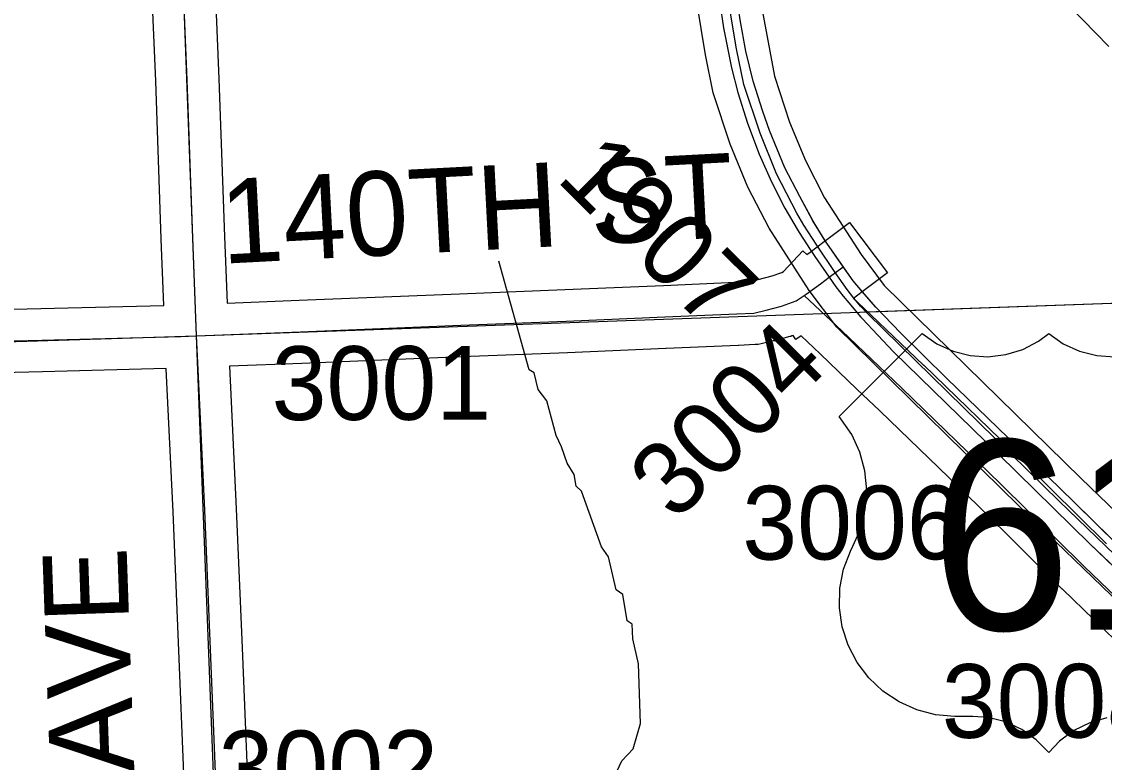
# Model space of a CAD drawing. Extents: x 128.7 to 185.5, y -21.4 to 12.6.
# Drawn here: x 145.758 to 146.785, y 0.252 to 0.955 of the extents above; entities that cross this region are included whole.
import ezdxf

# ---------------------------------------------------------------- set-up
doc = ezdxf.new("R2010")
doc.units = 0
for name, color, linetype in [('tdCoDivCarto', 7, 'Continuous'), ('tdCoHydroRiver', 7, 'Continuous'), ('tdCoPriCL', 7, 'Continuous'), ('tdCoPriDiv', 7, 'Continuous'), ('tdCoPrimary', 7, 'Continuous'), ('tdCoSecRdNmbr', 7, 'Continuous'), ('tdCoSecRdTxt', 7, 'Continuous'), ('tdCoSecRteBand', 7, 'Continuous'), ('tdCoSecRteCL', 7, 'Continuous'), ('tdCoSectLine', 7, 'Continuous'), ('tdCoSectLinePart', 7, 'Continuous'), ('tdCoShieldUsRte', 7, 'Continuous'), ('tdCoSurfConc', 7, 'Continuous'), ('tdCoSurfGravel', 7, 'Continuous'), ('tdCoTwpBndryShd', 7, 'Continuous')]:
    doc.layers.add(name, color=color, linetype=linetype)

msp = doc.modelspace()

# ---------------------------------------------------------------- linework, layer by layer
at = {"layer": 'tdCoDivCarto'}
for p, q in [((146.4204, 0.9729), (146.4238, 0.9497)), ((146.445, 0.9274), (146.4399, 0.957)), ((146.4238, 0.9497), (146.4317, 0.9115)), ((146.4522, 0.8988), (146.445, 0.9274)), ((146.4317, 0.9115), (146.4376, 0.8881)), ((146.4613, 0.87), (146.4522, 0.8988)), ((146.4376, 0.8881), (146.4468, 0.8592)), ((146.4675, 0.852), (146.4613, 0.87)), ((146.4468, 0.8592), (146.4579, 0.8296)), ((146.482, 0.8167), (146.4675, 0.852)), ((146.4579, 0.8296), (146.4695, 0.8035)), ((146.4963, 0.7893), (146.482, 0.8167)), ((146.4695, 0.8035), (146.482, 0.7783)), ((146.5087, 0.7664), (146.4963, 0.7893)), ((146.482, 0.7783), (146.4939, 0.7583)), ((146.5089, 0.7661), (146.5087, 0.7664)), ((146.5205, 0.7474), (146.5089, 0.7661)), ((146.5205, 0.7474), (146.5089, 0.7661)), ((146.4939, 0.7583), (146.4956, 0.7554)), ((146.4956, 0.7554), (146.5063, 0.7391)), ((146.522, 0.745), (146.5205, 0.7474)), ((146.5381, 0.722), (146.522, 0.745)), ((146.5063, 0.7391), (146.5106, 0.7325)), ((146.5106, 0.7325), (146.5241, 0.713)), ((146.5469, 0.7094), (146.5381, 0.722)), ((146.5241, 0.713), (146.5306, 0.7036)), ((146.5559, 0.699), (146.5469, 0.7094)), ((146.5306, 0.7036), (146.5375, 0.6947)), ((146.5686, 0.6843), (146.5559, 0.699)), ((146.5686, 0.6843), (146.5559, 0.699)), ((146.5375, 0.6947), (146.5428, 0.6885)), ((146.5428, 0.6885), (146.5543, 0.675)), ((146.5918, 0.6599), (146.5686, 0.6843)), ((146.5686, 0.6843), (146.5686, 0.6843)), ((146.5543, 0.675), (146.5556, 0.6736)), ((146.5556, 0.6736), (146.5851, 0.642)), ((146.6359, 0.6167), (146.5918, 0.6599)), ((146.5851, 0.642), (146.6852, 0.5445)), ((146.6941, 0.5602), (146.6359, 0.6167)), ((146.7568, 0.4993), (146.6941, 0.5602)), ((146.6852, 0.5445), (146.7716, 0.4597)), ((146.8187, 0.4382), (146.7568, 0.4993)), ((146.7716, 0.4597), (146.8253, 0.4082))]:
    msp.add_line(p, q, dxfattribs=at)
for points in [[(146.4075, 1.6164), (146.4085, 1.5347), (146.4105, 1.4153), (146.4127, 1.2861), (146.4145, 1.1657), (146.4157, 1.0553), (146.4187, 0.9919), (146.4204, 0.9729), (146.4238, 0.9497), (146.4317, 0.9115), (146.4376, 0.8881), (146.4468, 0.8592), (146.4579, 0.8296), (146.4695, 0.8035), (146.482, 0.7783), (146.4939, 0.7583)], [(146.4075, 1.6164), (146.4085, 1.5347), (146.4105, 1.4153), (146.4127, 1.2861), (146.4145, 1.1657), (146.4157, 1.0553), (146.4187, 0.9919), (146.4204, 0.9729), (146.4238, 0.9497), (146.4317, 0.9115), (146.4376, 0.8881), (146.4468, 0.8592), (146.4579, 0.8296), (146.4695, 0.8035), (146.482, 0.7783), (146.4939, 0.7583)], [(146.4075, 1.6164), (146.4085, 1.5347), (146.4105, 1.4153), (146.4127, 1.2861), (146.4145, 1.1657), (146.4157, 1.0553), (146.4187, 0.9919), (146.4204, 0.9729), (146.4238, 0.9497), (146.4317, 0.9115), (146.4376, 0.8881), (146.4468, 0.8592), (146.4579, 0.8296), (146.4695, 0.8035), (146.482, 0.7783), (146.4939, 0.7583)], [(146.5086, 0.7666), (146.4963, 0.7893), (146.482, 0.8167), (146.4675, 0.852), (146.4613, 0.87), (146.4522, 0.8988), (146.445, 0.9274), (146.4399, 0.957), (146.4367, 0.979), (146.4347, 1.0041), (146.4325, 1.0823), (146.4305, 1.194), (146.429, 1.3154), (146.4273, 1.4438), (146.4253, 1.5652), (146.4245, 1.6166)], [(146.5089, 0.7661), (146.5087, 0.7664), (146.4963, 0.7893), (146.482, 0.8167), (146.4675, 0.852), (146.4613, 0.87), (146.4522, 0.8988), (146.445, 0.9274), (146.4399, 0.957), (146.4367, 0.979), (146.4347, 1.0041), (146.4325, 1.0823), (146.4305, 1.194), (146.429, 1.3154), (146.4273, 1.4438), (146.4253, 1.5652), (146.4245, 1.6161)], [(146.5089, 0.7661), (146.5087, 0.7664), (146.4963, 0.7893), (146.482, 0.8167), (146.4675, 0.852), (146.4613, 0.87), (146.4522, 0.8988), (146.445, 0.9274), (146.4399, 0.957), (146.4367, 0.979), (146.4347, 1.0041), (146.4325, 1.0823), (146.4305, 1.194), (146.429, 1.3154), (146.4273, 1.4438), (146.4253, 1.5652), (146.4245, 1.6161)], [(146.5201, 0.7479), (146.5087, 0.7664), (146.5086, 0.7666)], [(146.5205, 0.7474), (146.5089, 0.7661)], [(146.4939, 0.7583), (146.4956, 0.7554), (146.5063, 0.7391)], [(146.4939, 0.7583), (146.4956, 0.7554), (146.5063, 0.7391)], [(146.4939, 0.7583), (146.4956, 0.7554), (146.5063, 0.7391)], [(146.5377, 0.7225), (146.522, 0.745), (146.5201, 0.7479)], [(146.5381, 0.722), (146.522, 0.745), (146.5205, 0.7474)], [(146.5381, 0.722), (146.522, 0.745), (146.5205, 0.7474)], [(146.5063, 0.7391), (146.5106, 0.7325), (146.5241, 0.713)], [(146.5063, 0.7391), (146.5106, 0.7325), (146.5241, 0.713)], [(146.5063, 0.7391), (146.5106, 0.7325), (146.5241, 0.713)], [(146.5555, 0.6994), (146.5469, 0.7094), (146.5377, 0.7225)], [(146.5559, 0.699), (146.5469, 0.7094), (146.5381, 0.722)], [(146.5559, 0.699), (146.5469, 0.7094), (146.5381, 0.722)], [(146.5241, 0.713), (146.5306, 0.7036), (146.5375, 0.6947), (146.5428, 0.6885)], [(146.5241, 0.713), (146.5306, 0.7036), (146.5375, 0.6947), (146.5428, 0.6885)], [(146.5241, 0.713), (146.5306, 0.7036), (146.5375, 0.6947), (146.5428, 0.6885)], [(146.5681, 0.6848), (146.5555, 0.6994)], [(146.5686, 0.6843), (146.5559, 0.699)], [(146.5428, 0.6885), (146.5543, 0.675), (146.5556, 0.6736)], [(146.5428, 0.6885), (146.5543, 0.675), (146.5556, 0.6736)], [(146.5428, 0.6885), (146.5543, 0.675), (146.5556, 0.6736)], [(147.272, -0.1789), (147.2579, -0.1522), (147.1908, -0.0252), (147.1661, 0.0212), (147.1348, 0.0779), (147.1131, 0.1124), (147.0872, 0.1514), (147.0751, 0.1681), (147.0554, 0.1948), (147.0253, 0.2315), (146.997, 0.2643), (146.9728, 0.2895), (146.9452, 0.3166), (146.9188, 0.3422), (146.8724, 0.3874), (146.8187, 0.4382), (146.7568, 0.4993), (146.6941, 0.5602), (146.6359, 0.6167), (146.5918, 0.6599), (146.5686, 0.6843), (146.5681, 0.6848)], [(147.2723, -0.1794), (147.2579, -0.1522), (147.1908, -0.0252), (147.1661, 0.0212), (147.1348, 0.0779), (147.1131, 0.1124), (147.0872, 0.1514), (147.0751, 0.1681), (147.0554, 0.1948), (147.0253, 0.2315), (146.997, 0.2643), (146.9728, 0.2895), (146.9452, 0.3166), (146.9188, 0.3422), (146.8724, 0.3874), (146.8187, 0.4382), (146.7568, 0.4993), (146.6941, 0.5602), (146.6359, 0.6167), (146.5918, 0.6599), (146.5686, 0.6843), (146.5686, 0.6843)], [(147.2723, -0.1794), (147.2579, -0.1522), (147.1908, -0.0252), (147.1661, 0.0212), (147.1348, 0.0779), (147.1131, 0.1124), (147.0872, 0.1514), (147.0751, 0.1681), (147.0554, 0.1948), (147.0253, 0.2315), (146.997, 0.2643), (146.9728, 0.2895), (146.9452, 0.3166), (146.9188, 0.3422), (146.8724, 0.3874), (146.8187, 0.4382), (146.7568, 0.4993), (146.6941, 0.5602), (146.6359, 0.6167), (146.5918, 0.6599), (146.5686, 0.6843), (146.5686, 0.6843)], [(146.5556, 0.6736), (146.5851, 0.642), (146.6852, 0.5445), (146.7716, 0.4597), (146.8253, 0.4082), (146.8719, 0.3638), (146.9775, 0.2585), (147.0302, 0.1986), (147.0421, 0.1835), (147.0724, 0.1423), (147.0951, 0.1081), (147.1124, 0.0812), (147.1294, 0.0513), (147.1607, -0.0051), (147.1824, -0.0463), (147.245, -0.1662), (147.2564, -0.1872)], [(146.5556, 0.6736), (146.5851, 0.642), (146.6852, 0.5445), (146.7716, 0.4597), (146.8253, 0.4082), (146.8719, 0.3638), (146.9775, 0.2585), (147.0302, 0.1986), (147.0421, 0.1835), (147.0724, 0.1423), (147.0951, 0.1081), (147.1124, 0.0812), (147.1294, 0.0513), (147.1607, -0.0051), (147.1824, -0.0463), (147.245, -0.1662), (147.2564, -0.1872)], [(146.5556, 0.6736), (146.5851, 0.642), (146.6852, 0.5445), (146.7716, 0.4597), (146.8253, 0.4082), (146.8719, 0.3638), (146.9775, 0.2585), (147.0302, 0.1986), (147.0421, 0.1835), (147.0724, 0.1423), (147.0951, 0.1081), (147.1124, 0.0812), (147.1294, 0.0513), (147.1607, -0.0051), (147.1824, -0.0463), (147.245, -0.1662), (147.2564, -0.1872)]]:
    msp.add_lwpolyline(points, dxfattribs=at)
at = {"layer": 'tdCoHydroRiver'}
for points in [[(146.7897, 0.9318), (146.7521, 0.97)], [(146.3186, 0.2346), (146.3275, 0.2538), (146.3381, 0.2652), (146.3452, 0.2891), (146.3434, 0.3459), (146.3379, 0.3694), (146.3374, 0.3836), (146.3326, 0.3866), (146.3286, 0.4117), (146.3221, 0.4162), (146.3148, 0.4475), (146.3082, 0.4568), (146.2891, 0.5098), (146.2842, 0.5144), (146.2823, 0.5254), (146.2756, 0.5362), (146.2703, 0.5518), (146.2653, 0.5627), (146.2563, 0.5955), (146.248, 0.6063), (146.2444, 0.622), (146.2395, 0.625), (146.2109, 0.7282)]]:
    msp.add_lwpolyline(points, dxfattribs=at)
at = {"layer": 'tdCoPriCL'}
msp.add_lwpolyline([(146.9277, 0.3216), (146.7425, 0.5002), (146.5605, 0.6785), (146.5539, 0.6852), (146.5477, 0.693), (146.5413, 0.7012), (146.53, 0.7173), (146.5125, 0.7434), (146.5001, 0.7623), (146.4935, 0.7737), (146.4743, 0.811), (146.4586, 0.8496), (146.4432, 0.8958), (146.4363, 0.9295), (146.4283, 0.9771)], dxfattribs=at)
at = {"layer": 'tdCoPriDiv'}
for points in [[(146.4582, 0.9803), (146.4722, 0.9036), (146.4867, 0.86), (146.5016, 0.8235), (146.5199, 0.7881), (146.5547, 0.7343), (146.5765, 0.7051), (146.7634, 0.5217), (146.9488, 0.3429)], [(146.9067, 0.3002), (146.7216, 0.4787), (146.5314, 0.6653), (146.5052, 0.7003), (146.4672, 0.7594), (146.447, 0.7984), (146.4304, 0.8392), (146.4142, 0.888), (146.4068, 0.924), (146.3985, 0.974)]]:
    msp.add_lwpolyline(points, dxfattribs=at)
at = {"layer": 'tdCoPrimary'}
for p, q in [((146.5205, 0.7474), (146.5089, 0.7661)), ((146.5205, 0.7474), (146.5089, 0.7661)), ((146.5686, 0.6843), (146.5559, 0.699)), ((146.5686, 0.6843), (146.5559, 0.699))]:
    msp.add_line(p, q, dxfattribs=at)
for points in [[(146.4075, 1.6164), (146.4085, 1.5347), (146.4105, 1.4153), (146.4127, 1.2861), (146.4145, 1.1657), (146.4157, 1.0553), (146.4187, 0.9919), (146.4204, 0.9729), (146.4238, 0.9497), (146.4317, 0.9115), (146.4376, 0.8881), (146.4468, 0.8592), (146.4579, 0.8296), (146.4695, 0.8035), (146.482, 0.7783), (146.4939, 0.7583)], [(146.4075, 1.6164), (146.4085, 1.5347), (146.4105, 1.4153), (146.4127, 1.2861), (146.4145, 1.1657), (146.4157, 1.0553), (146.4187, 0.9919), (146.4204, 0.9729), (146.4238, 0.9497), (146.4317, 0.9115), (146.4376, 0.8881), (146.4468, 0.8592), (146.4579, 0.8296), (146.4695, 0.8035), (146.482, 0.7783), (146.4939, 0.7583)], [(146.5089, 0.7661), (146.5087, 0.7664), (146.4963, 0.7893), (146.482, 0.8167), (146.4675, 0.852), (146.4613, 0.87), (146.4522, 0.8988), (146.445, 0.9274), (146.4399, 0.957), (146.4367, 0.979), (146.4347, 1.0041), (146.4325, 1.0823), (146.4305, 1.194), (146.429, 1.3154), (146.4273, 1.4438), (146.4253, 1.5652), (146.4245, 1.6161)], [(146.5089, 0.7661), (146.5087, 0.7664), (146.4963, 0.7893), (146.482, 0.8167), (146.4675, 0.852), (146.4613, 0.87), (146.4522, 0.8988), (146.445, 0.9274), (146.4399, 0.957), (146.4367, 0.979), (146.4347, 1.0041), (146.4325, 1.0823), (146.4305, 1.194), (146.429, 1.3154), (146.4273, 1.4438), (146.4253, 1.5652), (146.4245, 1.6161)], [(146.4204, 0.9729), (146.4238, 0.9497), (146.4317, 0.9115), (146.4376, 0.8881), (146.4468, 0.8592), (146.4579, 0.8296), (146.4695, 0.8035), (146.482, 0.7783), (146.4939, 0.7583), (146.4956, 0.7554), (146.5063, 0.7391), (146.5106, 0.7325), (146.5241, 0.713), (146.5306, 0.7036), (146.5375, 0.6947), (146.5428, 0.6885), (146.5543, 0.675), (146.5556, 0.6736), (146.5851, 0.642), (146.6852, 0.5445), (146.7716, 0.4597), (146.8253, 0.4082)], [(146.8187, 0.4382), (146.7568, 0.4993), (146.6941, 0.5602), (146.6359, 0.6167), (146.5918, 0.6599), (146.5686, 0.6843), (146.5686, 0.6843), (146.5559, 0.699), (146.5469, 0.7094), (146.5381, 0.722), (146.522, 0.745), (146.5205, 0.7474), (146.5089, 0.7661), (146.5087, 0.7664), (146.4963, 0.7893), (146.482, 0.8167), (146.4675, 0.852), (146.4613, 0.87), (146.4522, 0.8988), (146.445, 0.9274), (146.4399, 0.957)], [(146.4939, 0.7583), (146.4956, 0.7554), (146.5063, 0.7391)], [(146.4939, 0.7583), (146.4956, 0.7554), (146.5063, 0.7391)], [(146.5381, 0.722), (146.522, 0.745), (146.5205, 0.7474)], [(146.5381, 0.722), (146.522, 0.745), (146.5205, 0.7474)], [(146.5063, 0.7391), (146.5106, 0.7325), (146.5241, 0.713)], [(146.5063, 0.7391), (146.5106, 0.7325), (146.5241, 0.713)], [(146.5559, 0.699), (146.5469, 0.7094), (146.5381, 0.722)], [(146.5559, 0.699), (146.5469, 0.7094), (146.5381, 0.722)], [(146.5241, 0.713), (146.5306, 0.7036), (146.5375, 0.6947), (146.5428, 0.6885)], [(146.5241, 0.713), (146.5306, 0.7036), (146.5375, 0.6947), (146.5428, 0.6885)], [(146.5428, 0.6885), (146.5543, 0.675), (146.5556, 0.6736)], [(146.5428, 0.6885), (146.5543, 0.675), (146.5556, 0.6736)], [(147.2723, -0.1794), (147.2579, -0.1522), (147.1908, -0.0252), (147.1661, 0.0212), (147.1348, 0.0779), (147.1131, 0.1124), (147.0872, 0.1514), (147.0751, 0.1681), (147.0554, 0.1948), (147.0253, 0.2315), (146.997, 0.2643), (146.9728, 0.2895), (146.9452, 0.3166), (146.9188, 0.3422), (146.8724, 0.3874), (146.8187, 0.4382), (146.7568, 0.4993), (146.6941, 0.5602), (146.6359, 0.6167), (146.5918, 0.6599), (146.5686, 0.6843), (146.5686, 0.6843)], [(147.2723, -0.1794), (147.2579, -0.1522), (147.1908, -0.0252), (147.1661, 0.0212), (147.1348, 0.0779), (147.1131, 0.1124), (147.0872, 0.1514), (147.0751, 0.1681), (147.0554, 0.1948), (147.0253, 0.2315), (146.997, 0.2643), (146.9728, 0.2895), (146.9452, 0.3166), (146.9188, 0.3422), (146.8724, 0.3874), (146.8187, 0.4382), (146.7568, 0.4993), (146.6941, 0.5602), (146.6359, 0.6167), (146.5918, 0.6599), (146.5686, 0.6843), (146.5686, 0.6843)], [(146.5556, 0.6736), (146.5851, 0.642), (146.6852, 0.5445), (146.7716, 0.4597), (146.8253, 0.4082), (146.8719, 0.3638), (146.9775, 0.2585), (147.0302, 0.1986), (147.0421, 0.1835), (147.0724, 0.1423), (147.0951, 0.1081), (147.1124, 0.0812), (147.1294, 0.0513), (147.1607, -0.0051), (147.1824, -0.0463), (147.245, -0.1662), (147.2564, -0.1872)], [(146.5556, 0.6736), (146.5851, 0.642), (146.6852, 0.5445), (146.7716, 0.4597), (146.8253, 0.4082), (146.8719, 0.3638), (146.9775, 0.2585), (147.0302, 0.1986), (147.0421, 0.1835), (147.0724, 0.1423), (147.0951, 0.1081), (147.1124, 0.0812), (147.1294, 0.0513), (147.1607, -0.0051), (147.1824, -0.0463), (147.245, -0.1662), (147.2564, -0.1872)]]:
    msp.add_lwpolyline(points, dxfattribs=at)
at = {"layer": 'tdCoSecRteBand'}
for points in [[(144.9584, 0.6568), (145.0982, 0.6611), (145.2017, 0.6646), (145.2017, 0.6646), (145.2017, 0.6646), (145.3143, 0.6683), (145.4378, 0.6732), (145.4378, 0.6732), (145.4378, 0.6732), (145.5357, 0.6769), (145.5359, 0.6769), (145.5361, 0.6769), (145.6455, 0.6799), (145.6456, 0.6799), (145.6456, 0.6799), (145.7763, 0.6831), (145.8929, 0.6861), (145.8904, 0.7491), (145.8904, 0.7492), (145.8904, 0.7492), (145.8853, 0.8988), (145.8798, 1.0299)], [(145.9398, 1.0324), (145.9452, 0.9012), (145.9452, 0.9011), (145.9452, 0.901), (145.9504, 0.7514), (145.9529, 0.6883), (145.9529, 0.6883), (145.9529, 0.6883), (146.0215, 0.691), (146.1734, 0.6971), (146.1734, 0.6971), (146.1734, 0.6971), (146.2735, 0.7011), (146.3669, 0.705), (146.4354, 0.708), (146.4486, 0.7086), (146.457, 0.7106), (146.47, 0.7141), (146.4793, 0.7173), (146.4808, 0.7184), (146.4991, 0.7379), (146.503, 0.7343), (146.5062, 0.7367), (146.5195, 0.7467), (146.5434, 0.7648), (146.5796, 0.7169), (146.5556, 0.6988), (146.5474, 0.6926), (146.5568, 0.6837), (146.5569, 0.6836), (146.557, 0.6835), (146.5921, 0.65), (146.6137, 0.6293), (146.6138, 0.6292), (146.6139, 0.6292), (146.7073, 0.5387), (146.7074, 0.5385), (146.7075, 0.5384), (146.7873, 0.4597)], [(146.4926, 0.6538), (146.4901, 0.6575), (146.4888, 0.6571), (146.4878, 0.6567), (146.4868, 0.6565), (146.4722, 0.6525), (146.4717, 0.6524), (146.4712, 0.6523), (146.4596, 0.6495), (146.4569, 0.6489), (146.4541, 0.6488), (146.4381, 0.648), (146.4381, 0.648), (146.438, 0.648), (146.3695, 0.6451), (146.3695, 0.6451), (146.3694, 0.6451), (146.276, 0.6411), (146.2759, 0.6411), (146.2759, 0.6411), (146.1758, 0.6372), (146.0239, 0.631), (146.0239, 0.631), (146.0239, 0.631), (145.9553, 0.6283), (145.9617, 0.493), (145.9617, 0.4929), (145.9617, 0.4928), (145.9669, 0.3685), (145.9669, 0.3685), (145.9669, 0.3685), (145.9723, 0.2361)], [(146.8057, 0.3586), (146.7455, 0.4166), (146.7454, 0.4167), (146.7453, 0.4168), (146.6655, 0.4957), (146.5722, 0.586), (146.5506, 0.6066), (146.5156, 0.6401), (146.4975, 0.6571), (146.4926, 0.6538)], [(145.7456, -0.323), (145.8648, -0.319), (145.9316, -0.3163), (145.9299, -0.2754), (145.9245, -0.1447), (145.9245, -0.1447), (145.9245, -0.1446), (145.9191, -0.0098), (145.919, -0.0095), (145.919, -0.0093), (145.9161, 0.1112), (145.9124, 0.2338), (145.907, 0.366), (145.9018, 0.4902), (145.8953, 0.626), (145.8953, 0.626), (145.8953, 0.626), (145.8953, 0.626), (145.8953, 0.6262), (145.7778, 0.6231), (145.7778, 0.6231), (145.7778, 0.6231), (145.6471, 0.6199)]]:
    msp.add_lwpolyline(points, dxfattribs=at)
at = {"layer": 'tdCoSecRteCL'}
for points in [[(145.9241, 0.6571), (145.9204, 0.7503), (145.9152, 0.9), (145.9098, 1.0311), (145.9046, 1.1586), (145.8985, 1.2896), (145.893, 1.423), (145.8896, 1.554), (145.8865, 1.6603)], [(146.5005, 0.6955), (146.5023, 0.6968), (146.5161, 0.7066), (146.5243, 0.7128), (146.5375, 0.7228)], [(145.9241, 0.6571), (146.0227, 0.661), (146.1746, 0.6672), (146.2747, 0.6711), (146.3682, 0.6751), (146.4367, 0.678), (146.4528, 0.6788), (146.4644, 0.6815), (146.4789, 0.6854), (146.493, 0.6903), (146.5005, 0.6955)], [(146.8265, 0.3802), (146.7663, 0.4382), (146.6864, 0.5171), (146.593, 0.6076), (146.5713, 0.6283), (146.5363, 0.6619), (146.5005, 0.6955)], [(144.9294, 0.6259), (144.9401, 0.6262), (145.0991, 0.6312), (145.2027, 0.6346), (145.3154, 0.6383), (145.439, 0.6432), (145.5369, 0.6469), (145.6464, 0.6499), (145.7771, 0.6531), (145.9092, 0.6566), (145.9241, 0.6571)], [(145.9628, -0.3451), (145.9599, -0.2741), (145.9545, -0.1434), (145.949, -0.0085), (145.9461, 0.112), (145.9424, 0.2349), (145.9369, 0.3673), (145.9318, 0.4916), (145.9251, 0.6314), (145.9241, 0.6571)]]:
    msp.add_lwpolyline(points, dxfattribs=at)
at = {"layer": 'tdCoSectLine'}
for points in [[(145.8861, 1.6603), (145.9237, 0.6571)], [(145.9237, 0.6571), (146.9256, 0.693)], [(144.929, 0.6259), (145.9237, 0.6571)], [(145.9237, 0.6571), (145.9624, -0.3451)]]:
    msp.add_lwpolyline(points, dxfattribs=at)
at = {"layer": 'tdCoSectLinePart'}
msp.add_lwpolyline([(146.5601, 0.6799), (146.9256, 0.693)], dxfattribs=at)
at = {"layer": 'tdCoShieldUsRte'}
msp.add_lwpolyline([(146.7876, 0.2944), (146.7714, 0.2898), (146.7562, 0.2824), (146.7426, 0.2723), (146.7325, 0.2617), (146.7207, 0.2738), (146.7069, 0.2835), (146.6916, 0.2906), (146.6752, 0.2948), (146.6606, 0.2959), (146.6435, 0.2959), (146.6251, 0.2975), (146.6073, 0.3021), (146.5905, 0.3096), (146.5752, 0.3198), (146.5618, 0.3324), (146.5507, 0.3471), (146.5422, 0.3634), (146.5366, 0.3809), (146.5339, 0.3991), (146.5344, 0.4175), (146.5379, 0.4356), (146.5444, 0.4528), (146.5468, 0.4576), (146.5541, 0.4744), (146.5585, 0.4923), (146.5598, 0.5107), (146.5581, 0.529), (146.5533, 0.5467), (146.5456, 0.5635), (146.5336, 0.5805), (146.6125, 0.6594), (146.6263, 0.6497), (146.6417, 0.6426), (146.6581, 0.6385), (146.6749, 0.6374), (146.6917, 0.6393), (146.7079, 0.6443), (146.7228, 0.6522), (146.7325, 0.6594), (146.7463, 0.6497), (146.7617, 0.6426), (146.7781, 0.6385), (146.7949, 0.6374)], dxfattribs=at)
at = {"layer": 'tdCoSurfConc'}
msp.add_lwpolyline([(146.9133, 0.2944), (146.8889, 0.321), (146.8436, 0.364), (146.8265, 0.3802), (146.7663, 0.4382), (146.6864, 0.5171), (146.593, 0.6076), (146.5713, 0.6283), (146.5363, 0.6619), (146.5005, 0.6955), (146.5023, 0.6968), (146.5161, 0.7066), (146.5243, 0.7128), (146.5375, 0.7228)], dxfattribs=at)
at = {"layer": 'tdCoSurfGravel'}
for points in [[(145.9628, -0.3451), (145.9599, -0.2741), (145.9545, -0.1434), (145.949, -0.0085), (145.9461, 0.112), (145.9424, 0.2349), (145.9369, 0.3673), (145.9318, 0.4916), (145.9251, 0.6314), (145.9241, 0.6571), (145.9204, 0.7503), (145.9152, 0.9), (145.9098, 1.0311), (145.9046, 1.1586), (145.8985, 1.2896), (145.893, 1.423), (145.8896, 1.554), (145.8865, 1.6603)], [(144.9401, 0.6262), (145.0991, 0.6312), (145.2027, 0.6346), (145.3154, 0.6383), (145.439, 0.6432), (145.5369, 0.6469), (145.6464, 0.6499), (145.7771, 0.6531), (145.9092, 0.6566), (145.9241, 0.6571), (146.0227, 0.661), (146.1746, 0.6672), (146.2747, 0.6711), (146.3682, 0.6751), (146.4367, 0.678), (146.4528, 0.6788), (146.4644, 0.6815), (146.4789, 0.6854), (146.493, 0.6903), (146.5005, 0.6955)]]:
    msp.add_lwpolyline(points, dxfattribs=at)
at = {"layer": 'tdCoTwpBndryShd'}
msp.add_lwpolyline([(145.7753, 4.6779), (145.8126, 3.6695), (145.8481, 2.667), (145.8861, 1.6603), (145.9237, 0.6571), (145.9624, -0.3451), (146.001, -1.3445), (146.0324, -2.3549), (146.0614, -3.3563), (146.0903, -4.356), (146.1189, -5.3582), (146.1498, -6.358), (146.1796, -7.3579)], dxfattribs=at)

# ---------------------------------------------------------------- texts
at = {"layer": 'tdCoSecRdNmbr'}
for s, rotation, p in [('1907', 315.1106, (146.264, 0.8056)), ('3004', 45.1101, (146.3785, 0.4797)), ('3001', 0.111, (145.9953, 0.5772)), ('3006', 0.1114, (146.4418, 0.4447)), ('3008', 0.1115, (146.6311, 0.2755)), ('3002', 0.111, (145.945, 0.2123))]:
    msp.add_text(s, height=0.07, rotation=rotation, dxfattribs=at).set_placement(p)
at = {"layer": 'tdCoSecRdTxt'}
for s, rotation, p in [('140TH ST', 2.9929, (145.9486, 0.7256)), ('220TH AVE', 92, (145.8773, -0.1073))]:
    msp.add_text(s, height=0.08, rotation=rotation, dxfattribs=at).set_placement(p)
at = {"layer": 'tdCoShieldUsRte'}
msp.add_text('61', height=0.18, dxfattribs=at).set_placement((146.6201, 0.3781))

doc.saveas('drawing.dxf')
